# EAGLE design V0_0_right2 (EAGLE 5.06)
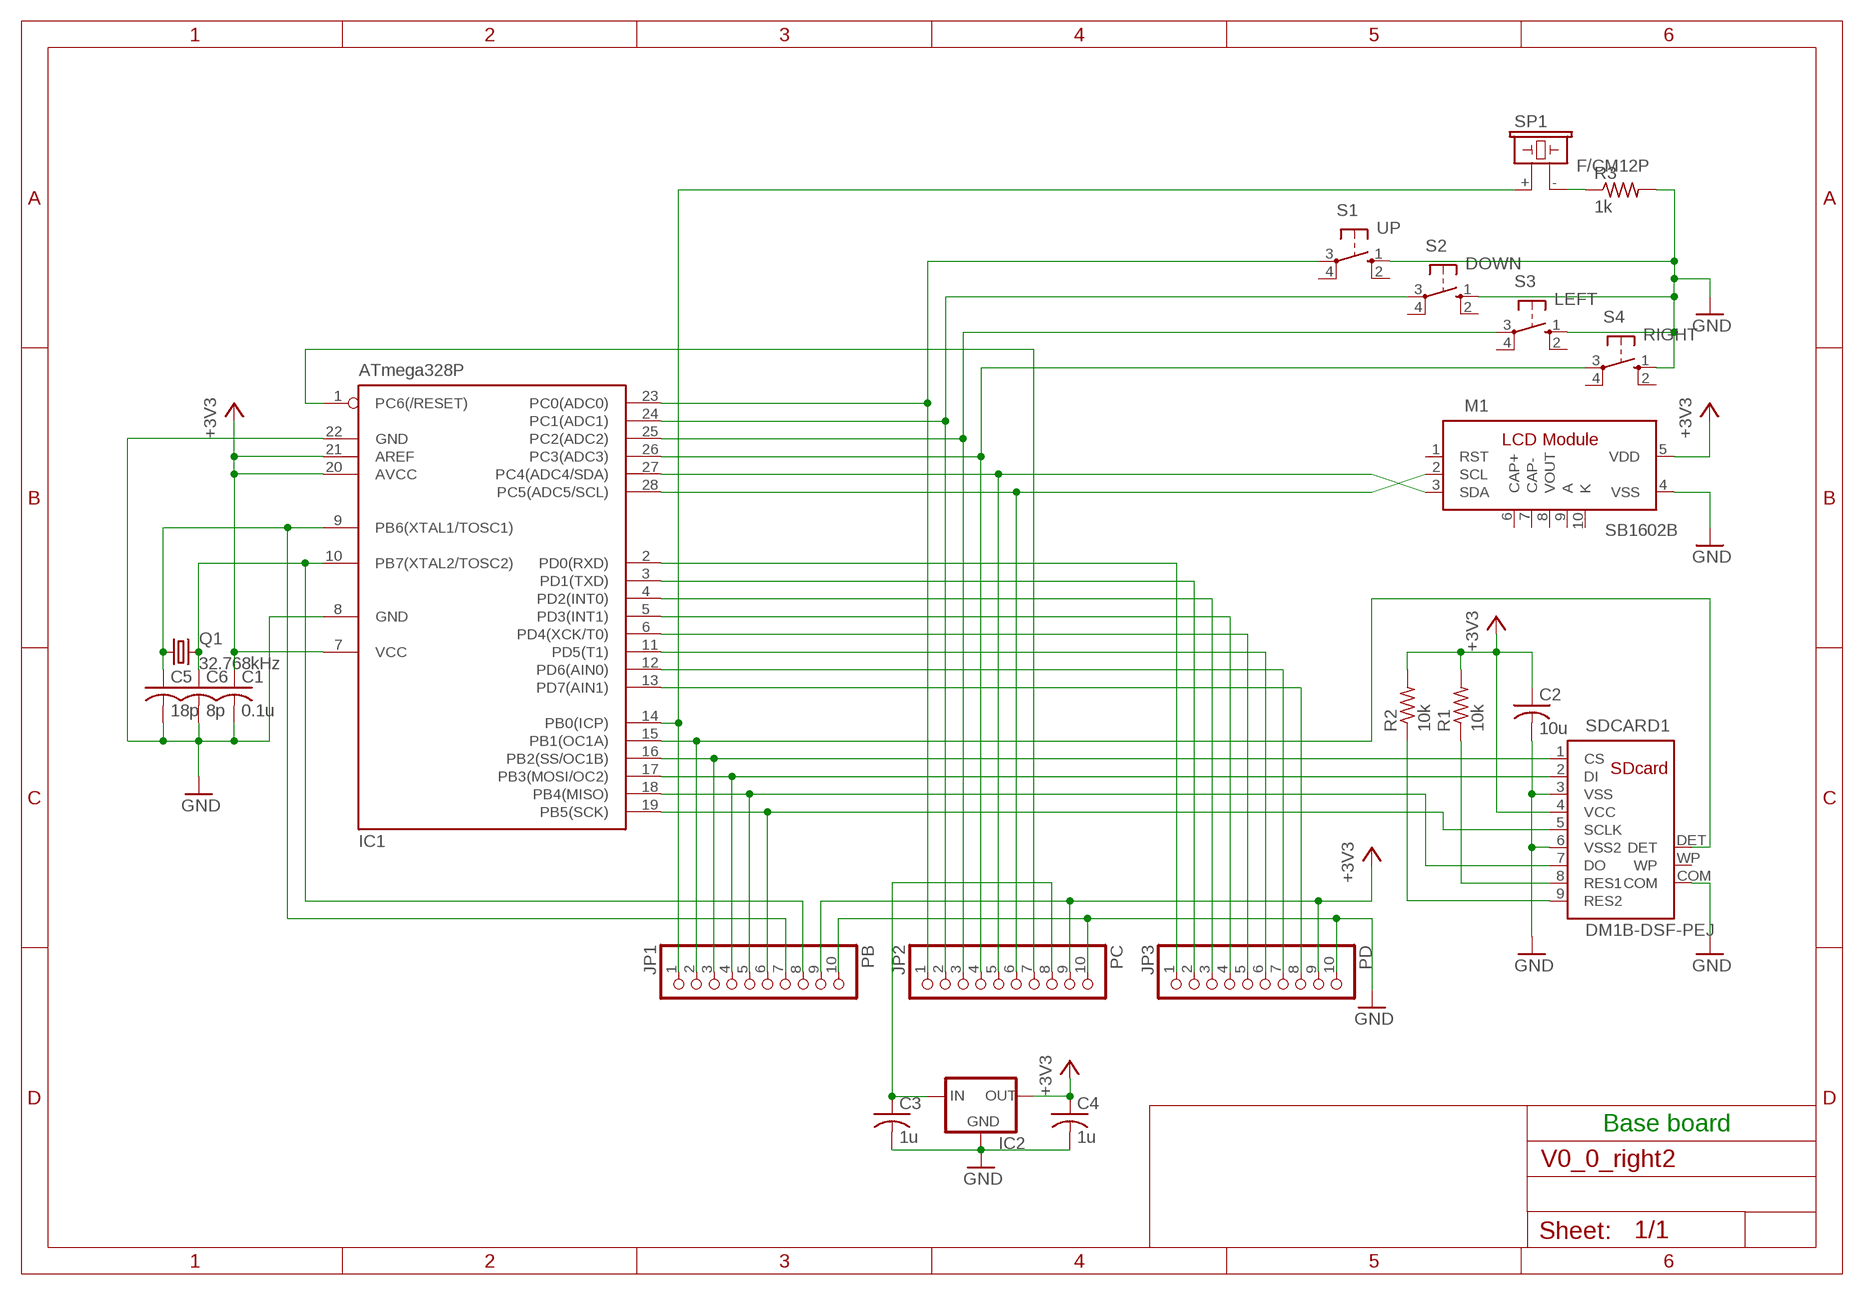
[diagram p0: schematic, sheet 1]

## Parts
C1  0.1u  C-US025-024X044  [C025-024X044]
C2  10u  C-US025-024X044  [C025-024X044]
C3  1u  C-US025-024X044  [C025-024X044]
C4  1u  C-US025-024X044  [C025-024X044]
C5  18p  C-US025-024X044  [C025-024X044]
C6  8p  C-US025-024X044  [C025-024X044]
IC1  ATmega328P  MEGA8-P  [DIL28-3]
IC2  XC63FPL  [TO92]
JP1  PB  PINHD-1X10  [1X10]
JP2  PC  PINHD-1X10  [1X10]
JP3  PD  PINHD-1X10  [1X10]
M1  SB1602B  [SB1602B]
Q1  32.768kHz  CRYSTALTC26H  [TC26H]
R1  10k  R-US_0204/5  [0204/5]
R2  10k  R-US_0204/5  [0204/5]
R3  1k  R-US_0204/5  [0204/5]
S1  UP  10-XX  [B3F-10XX]
S2  DOWN  10-XX  [B3F-10XX]
S3  LEFT  10-XX  [B3F-10XX]
S4  RIGHT  10-XX  [B3F-10XX]
SDCARD1  DM1B-DSF-PEJ  [DM1B]
SP1  F/CM12P  [F/CM12P]

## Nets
+3V3: C1.1 C2.1 C4.1 IC1.7(VCC) IC1.20(AVCC) IC1.21(AREF) IC2.3(OUT) JP1.9 JP2.9 JP3.9 M1.5(VDD) R1.2 R2.2 SDCARD1.4(VCC)
GND: C1.2 C2.2 C3.2 C4.2 C5.2 C6.2 IC1.8(GND) IC1.22(GND) IC2.2(GND) JP1.10 JP2.10 JP3.10 M1.4(VSS) R3.2 S1.1(S) S2.1(S) S3.1(S) S4.1(S) SDCARD1.3(VSS) SDCARD1.6(VSS2) SDCARD1.COM
N$1: IC1.16(PB2(SS/OC1B)) JP1.3 SDCARD1.1(CS)
N$2: IC1.17(PB3(MOSI/OC2)) JP1.4 SDCARD1.2(DI)
N$3: IC1.18(PB4(MISO)) JP1.5 SDCARD1.7(DO)
N$4: IC1.19(PB5(SCK)) JP1.6 SDCARD1.5(SCLK)
N$5: IC1.27(PC4(ADC4/SDA)) JP2.5 M1.3(SDA)
N$6: IC1.28(PC5(ADC5/SCL)) JP2.6 M1.2(SCL)
N$7: IC1.2(PD0(RXD)) JP3.1
N$8: IC1.3(PD1(TXD)) JP3.2
N$9: R1.1 SDCARD1.8(RES1)
N$10: R2.1 SDCARD1.9(RES2)
N$11: IC1.4(PD2(INT0)) JP3.3
N$12: IC1.5(PD3(INT1)) JP3.4
N$13: IC1.6(PD4(XCK/T0)) JP3.5
N$14: IC1.11(PD5(T1)) JP3.6
N$15: IC1.12(PD6(AIN0)) JP3.7
N$16: IC1.13(PD7(AIN1)) JP3.8
N$17: R3.1 SP1.-
N$18: IC1.23(PC0(ADC0)) JP2.1 S1.3(P)
N$19: IC1.24(PC1(ADC1)) JP2.2 S2.3(P)
N$20: IC1.25(PC2(ADC2)) JP2.3 S3.3(P)
N$21: IC1.26(PC3(ADC3)) JP2.4 S4.3(P)
N$22: IC1.14(PB0(ICP)) JP1.1 SP1.+
N$23: IC1.15(PB1(OC1A)) JP1.2 SDCARD1.DET
N$24: C5.1 IC1.9(PB6(XTAL1/TOSC1)) JP1.7 Q1.1
N$26: IC1.1(PC6(/RESET)) JP2.7
N$27: C3.1 IC2.1(IN) JP2.8
N$28: C6.1 IC1.10(PB7(XTAL2/TOSC2)) JP1.8 Q1.2
Unconnected: M1.1(RST) M1.6(CAP+) M1.7(CAP-) M1.8(VOUT) S1.2(S1) S1.4(P1) S2.2(S1) S2.4(P1) S3.2(S1) S3.4(P1) S4.2(S1) S4.4(P1) SDCARD1.WP

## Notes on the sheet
- Base board

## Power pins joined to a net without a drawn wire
A: M1.9(A)
K: M1.10(K)

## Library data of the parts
C1-C6 = rcl:C-US: CAPACITOR, American symbol
IC1 = atmel:MEGA8-P: MICROCONTROLLER 8 Kbytes FLASH, 1 kbytes SRAM, 512 bytes EEPROM, USART, 4-channel 10 bit ADC, 2-channel 8 bit ADC Pin compatible with Atmega48, ATMega88, ATMega168 Source: avr.lbr
IC2 = v-reg:XC63FP: Positiv Voltage Regulators www.torex.co.jp/english/product/pro02/pdf/0201_xc62fp.pdf
JP1-JP3 = pinhead:PINHD-1X10: PIN HEADER
M1 = TOG:SB1602B: Strawberry Linux Co.,Ltd. I2C LCD Module Controler: ST7032i
Q1 = crystal:CRYSTAL: CRYSTAL
R1-R3 = rcl:R-US_: RESISTOR, American symbol
S1-S4 = switch-omron:10-XX: OMRON SWITCH
SDCARD1 = TOG:DM1B-DSF-PEJ: SDcard connector reverse type HIROSE
SP1 = buzzer:F/CM12P: BUZZER

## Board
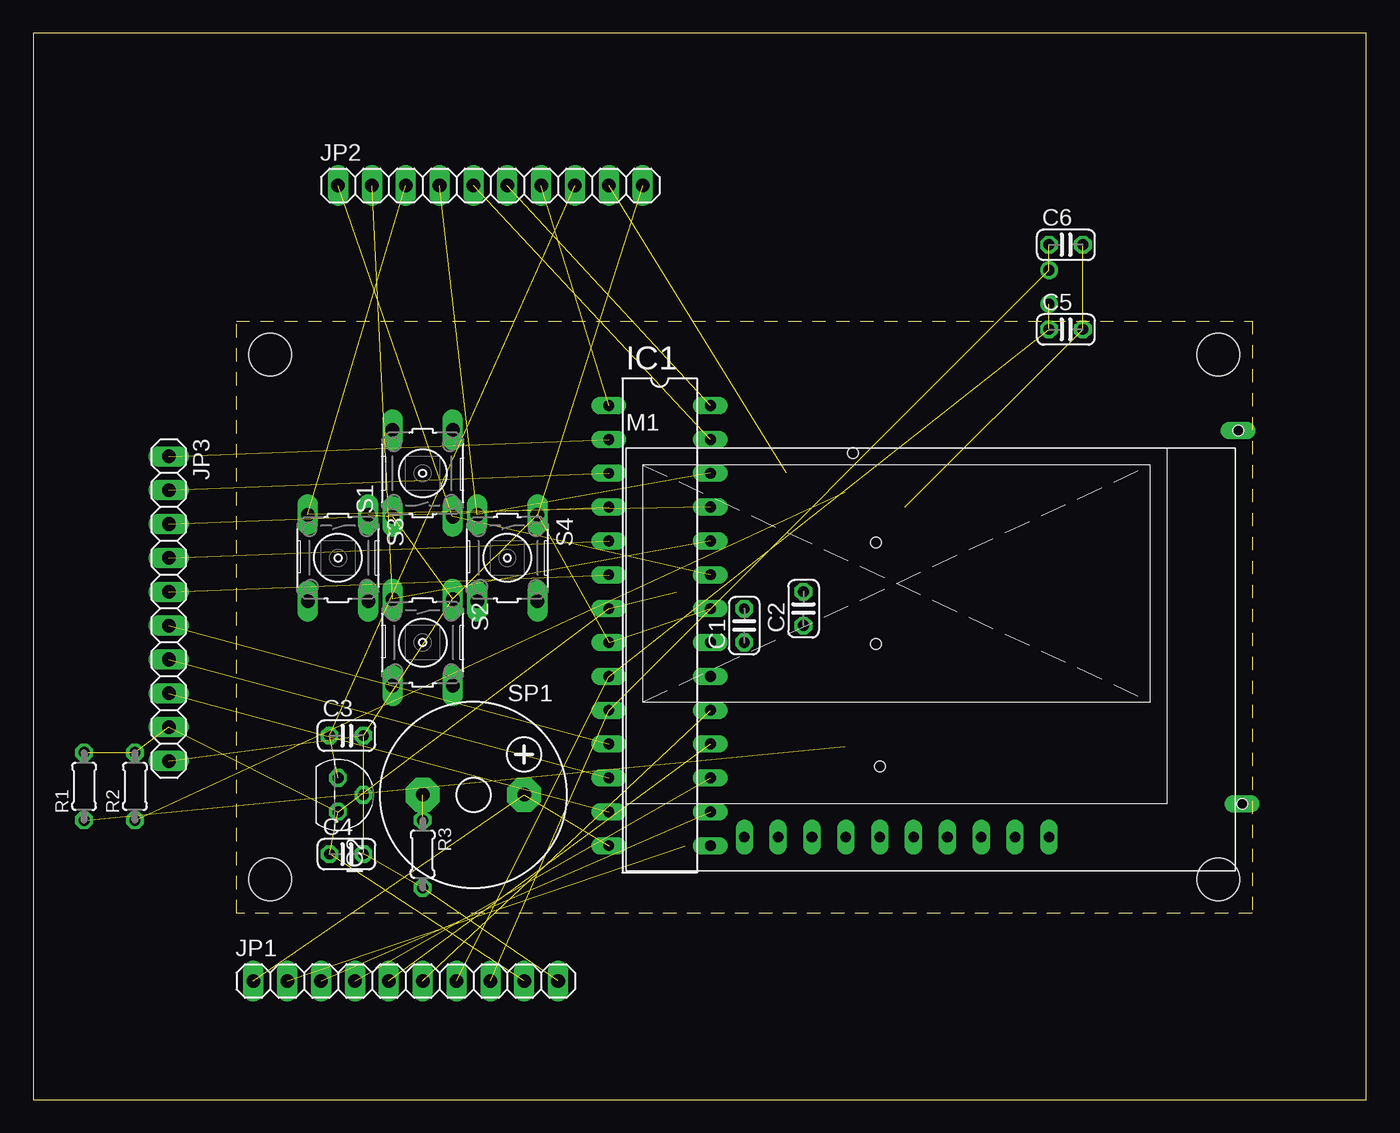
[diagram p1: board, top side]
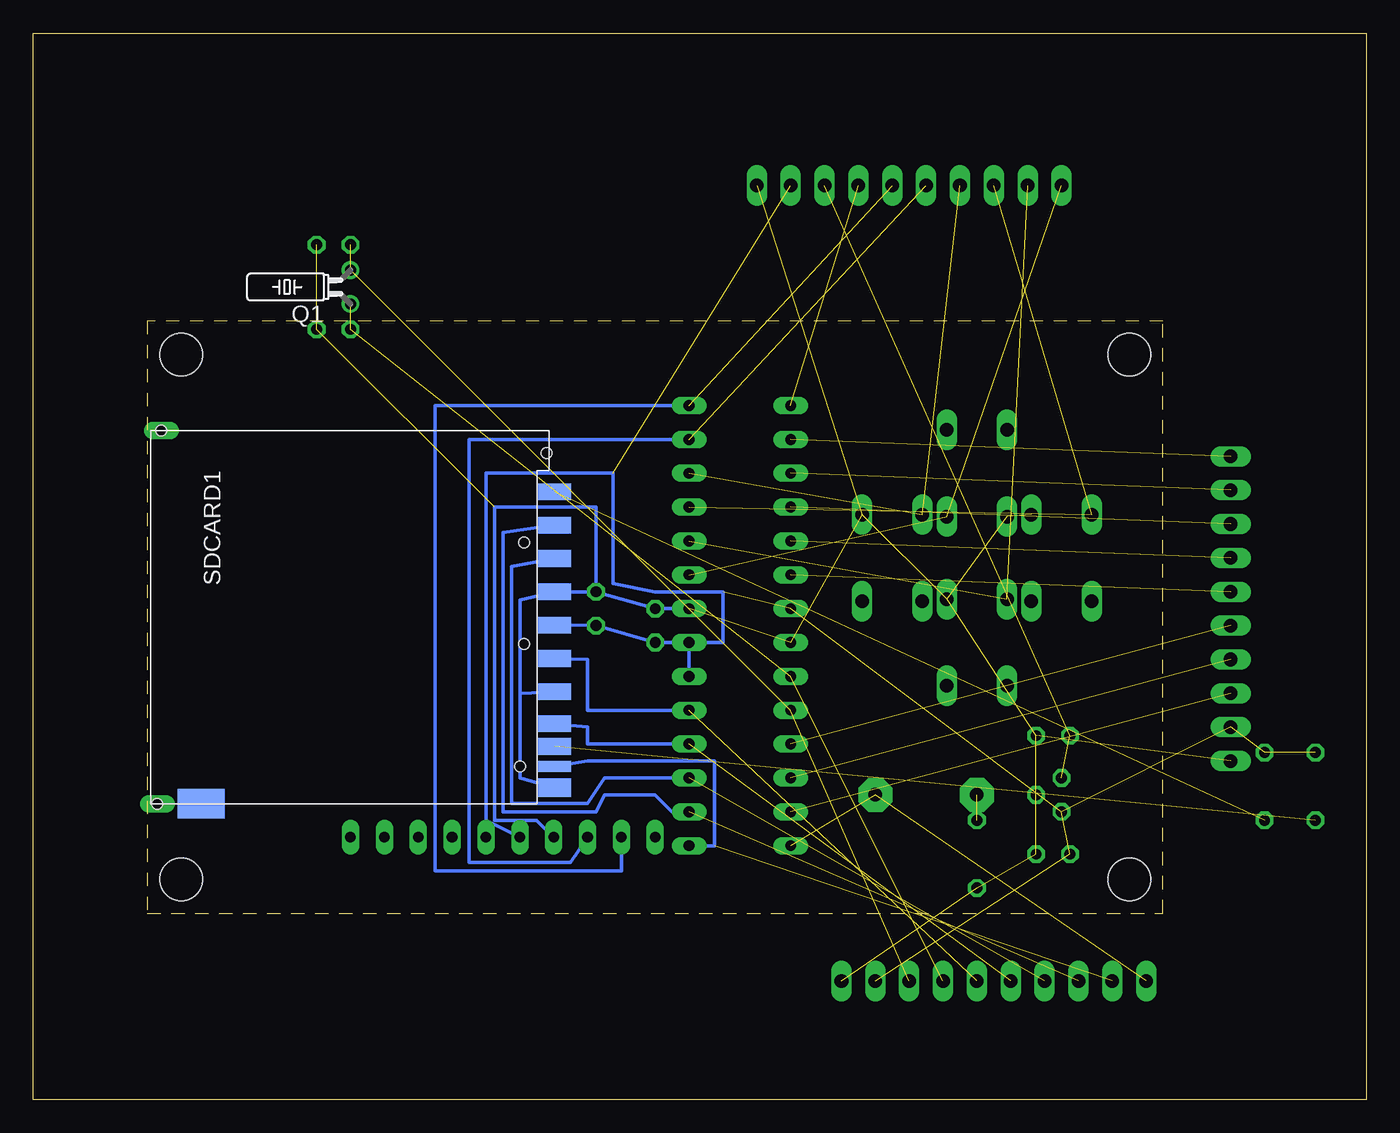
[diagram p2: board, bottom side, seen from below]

Size 100 x 80 mm. Coordinates in mm from the lower left corner, seen from the top.
Outline: 0,0 100,0 100,80 0,80 0,0
Outline: 15.24,58.42 91.44,58.42 91.44,13.97 15.24,13.97 15.24,58.42
Copper layers (1*16): Top 0.035mm / dielectric 1.5mm / Bottom 0.035mm
Design rules "default": minimum track width 10mil, minimum drill 24mil, track to track 8mil, track to pad 8mil, pad to pad 8mil, via to via 8mil, smd to smd 8mil, copper to edge 40mil, drill to drill 8mil, minimum pad ring 10mil, minimum via ring 8mil, stop-mask expansion 4mil, vias tented up to drill 0mil, thermal gap 10mil
Holes 3.2 mm at 17.78,55.88 88.9,55.88 88.9,16.51 17.78,16.51

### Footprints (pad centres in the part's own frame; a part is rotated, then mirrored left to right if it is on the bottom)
C025-024X044 = drill 0.813 octagon: 1 -1.27,0; 2 1.27,0
DIL28-3 = drill 0.813 long: 1 -16.51,-3.81; 2 -13.97,-3.81; 3 -11.43,-3.81; 4 -8.89,-3.81; 5 -6.35,-3.81; 6 -3.81,-3.81; 7 -1.27,-3.81; 8 1.27,-3.81; 9 3.81,-3.81; 10 6.35,-3.81; 11 8.89,-3.81; 12 11.43,-3.81; 13 13.97,-3.81; 14 16.51,-3.81; 15 16.51,3.81; 16 13.97,3.81; 17 11.43,3.81; 18 8.89,3.81; 19 6.35,3.81; 20 3.81,3.81; 21 1.27,3.81; 22 -1.27,3.81; 23 -3.81,3.81; 24 -6.35,3.81; 25 -8.89,3.81; 26 -11.43,3.81; 27 -13.97,3.81; 28 -16.51,3.81
TO92 = drill 0.813 octagon: 1 -1.27,0; 2 0,1.905; 3 1.27,0
1X10 = drill 1.016 long: 1 -11.43,0; 2 -8.89,0; 3 -6.35,0; 4 -3.81,0; 5 -1.27,0; 6 1.27,0; 7 3.81,0; 8 6.35,0; 9 8.89,0; 10 11.43,0
SB1602B = drill 0.8 long: 1 -13.97,-12.7; 2 -11.43,-12.7; 3 -8.89,-12.7; 4 -6.35,-12.7; 5 -3.81,-12.7; 6 -1.27,-12.7; 7 1.27,-12.7; 8 3.81,-12.7; 9 6.35,-12.7; 10 8.89,-12.7
TC26H = drill 0.813 round: 1 -1.27,0; 2 1.27,0
0204/5 = drill 0.813 octagon: 1 -2.54,0; 2 2.54,0
B3F-10XX = drill 1.016 long: 1 -3.251,2.261; 2 3.251,2.261; 3 -3.251,-2.261; 4 3.251,-2.261
DM1B = smd 1.25 x 2.5: 1 -6.9,15.3; 2 -4.4,15.3; 3 -1.9,15.3; 4 0.6,15.3; 5 3.1,15.3; 6 5.6,15.3; 7 8,15.3; 8 9.7,15.3; 9 -9.4,15.3 | smd 1.4 x 2.5: COM 12.8,15.3 | smd 0.8 x 2.5: DET 11.2,15.3 | drill 0.8 pad 1.2 long: P$17 14,-14.5 | drill 0.8 pad 1.27 long: P$18 -14,-14.2 | smd 2.2 x 3.5: WP 14,-11.2 | hole 0.8: -12.3,14.7; -5.6,13; 2,13; 11.2,12.7; -14,-14.2; 14,-14.5
F/CM12P = drill 1.016 pad 2.54 octagon: + 3.81,0; - -3.81,0

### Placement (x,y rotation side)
C1  53.34,35.56 90 top
C2  57.78,36.83 90 top
C3  23.5,27.3 0 top
C4  23.5,18.41 0 top
C5  77.47,57.78 0 top
C6  77.47,64.14 0 top
IC1  46.99,35.56 270 top
IC2  22.86,22.86 270 top
JP1  27.94,8.89 0 top
JP2  34.29,68.58 0 top
JP3  10.16,36.83 270 top
M1  67.31,32.38 0 top
Q1  76.2,60.96 90 bottom
R1  3.81,23.5 90 top
R2  7.62,23.5 90 top
R3  29.21,18.41 270 top
S1  29.21,46.99 90 top
S2  29.21,34.29 270 top
S3  22.86,40.64 270 top
S4  35.56,40.64 270 top
SDCARD1  76.2,36.2 270 bottom
SP1  33.02,22.86 0 top

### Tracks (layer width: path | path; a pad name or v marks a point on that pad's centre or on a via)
+3V3  (8 unrouted)
  Bottom 0.254: SDCARD1.4 C2.1 C1.1 IC1.21 | IC1.20 IC1.21 | M1.5 66.04,20.95 66.04,46.99 56.52,46.99 56.52,38.73 53.34,38.1 48.26,38.1 48.26,34.29 IC1.21
GND  (14 unrouted)
  Bottom 0.254: 63.5,30.48 63.5,24.13 SDCARD1.COM | 63.5,30.48 63.5,37.47 SDCARD1.3 C2.2 | 63.5,30.48 SDCARD1.6 | C2.2 C1.2 IC1.22 | M1.4 62.23,20.95 65.41,20.95 65.41,44.45 57.78,44.45 C2.2
N$1  (1 unrouted)
  Bottom 0.254: SDCARD1.1 64.77,42.55 64.77,21.59 57.78,21.59 57.15,22.86 53.34,22.86 52.07,21.59 IC1.16
N$2  (1 unrouted)
  Bottom 0.254: SDCARD1.2 64.14,40.01 64.14,22.23 58.42,22.23 57.15,24.13 IC1.17
N$3  (1 unrouted)
  Bottom 0.254: IC1.18 58.42,26.67 58.42,27.94 SDCARD1.7
N$4  (1 unrouted)
  Bottom 0.254: IC1.19 58.42,29.21 58.42,33.02 SDCARD1.5
N$5  (1 unrouted)
  Bottom 0.254: IC1.27 67.31,49.53 67.31,17.78 59.69,17.78 M1.3
N$6  (1 unrouted)
  Bottom 0.254: M1.2 55.88,17.14 69.85,17.14 69.85,52.07 IC1.28
N$7  (1 unrouted)
N$8  (1 unrouted)
N$9  (1 unrouted)
N$10  (1 unrouted)
N$11  (1 unrouted)
N$12  (1 unrouted)
N$13  (1 unrouted)
N$14  (1 unrouted)
N$15  (1 unrouted)
N$16  (1 unrouted)
N$17  (1 unrouted)
N$18  (2 unrouted)
N$19  (2 unrouted)
N$20  (2 unrouted)
N$21  (2 unrouted)
N$22  (2 unrouted)
N$23  (1 unrouted)
  Bottom 0.254: SDCARD1.DET 58.42,25.4 48.9,25.4 48.9,19.05 IC1.15
N$24  (3 unrouted)
N$26  (1 unrouted)
N$27  (2 unrouted)
N$28  (3 unrouted)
